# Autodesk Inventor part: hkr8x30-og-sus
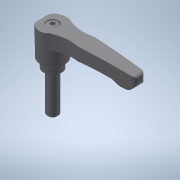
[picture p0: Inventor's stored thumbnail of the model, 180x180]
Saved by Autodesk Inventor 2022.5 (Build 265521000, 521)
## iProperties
Created: 2017-09
Part Number: hkr8x30-og-sus
Material: 一般
Document SubType Name: Modeling
Designer: imaocorp
Density: 1 g/cm^3
Appearance: 既定
Author: imaocorp
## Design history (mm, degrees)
node "hkr8x30-og-sus.x_t1"
node "hkr8x30-og-sus"
node "Base1"
